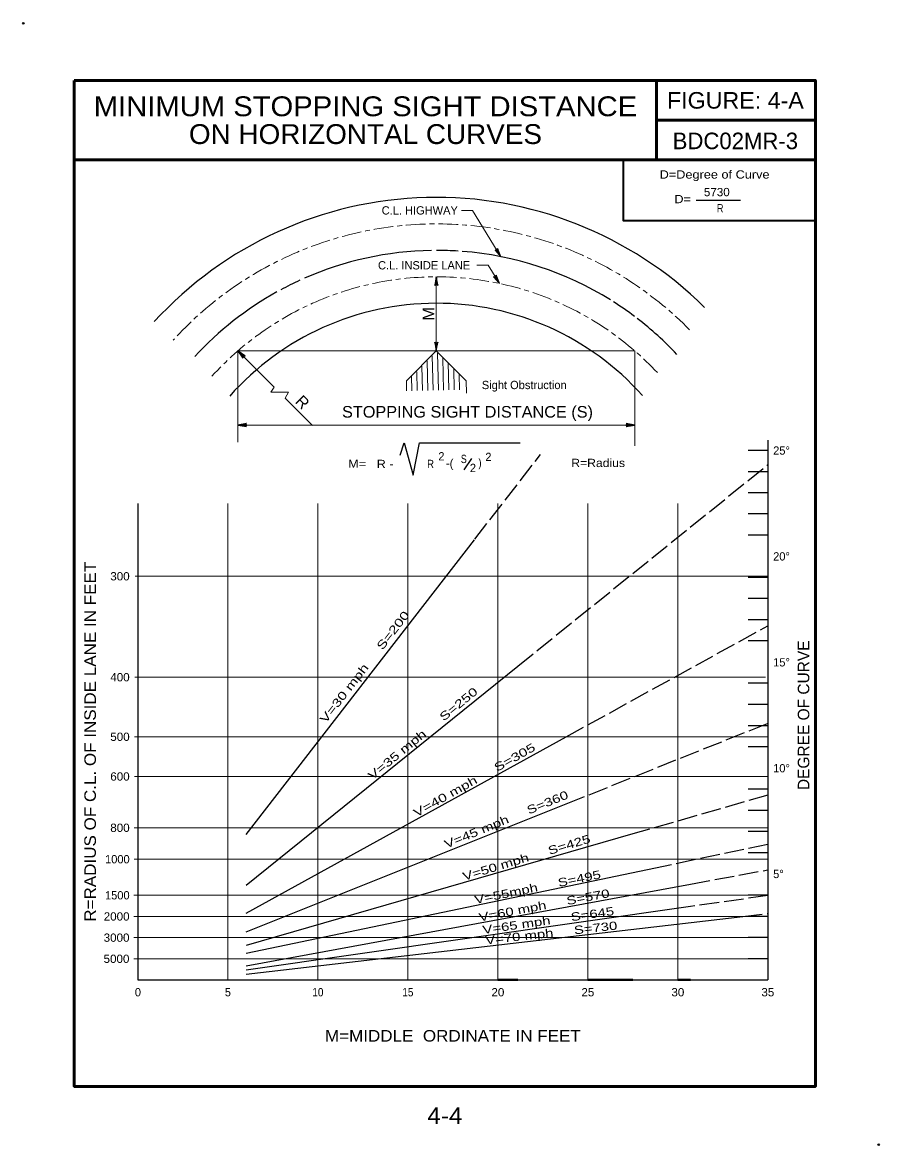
# Model space of a CAD drawing. Extents: x -960 to -151, y 1600 to 2660.
import ezdxf
from ezdxf.enums import TextEntityAlignment as Align

# ---------------------------------------------------------------- set-up
doc = ezdxf.new("R2010")
doc.units = 0
doc.header["$LTSCALE"] = 3.1
doc.header["$PDMODE"] = 32
doc.header["$PDSIZE"] = 1.55
doc.linetypes.add('LONG_DASH_SHORT_DASH', pattern=[9.9, 6, -1.2, 1.5, -1.2])
doc.linetypes.add('LONG_DASHED', pattern=[7.5, 6, -1.5])
doc.layers.add('1', color=7, linetype='Continuous', lineweight=25)
doc.layers.add('24', color=7, linetype='Continuous', lineweight=25)

msp = doc.modelspace()

# ---------------------------------------------------------------- linework, layer by layer
at = {"layer": '1', "lineweight": 53}
for p, q in [((-361.39, 2605.66), (-361.39, 2530.66)), ((-361.39, 2568.16), (-212.6, 2568.16)), ((-911.39, 2530.66), (-211.39, 2530.66))]:
    msp.add_line(p, q, dxfattribs=at)
at = {"layer": '1'}
for p, q in [((-324.14, 2492.71), (-282.05, 2492.71)), ((-256.31, 2265.94), (-256.31, 2256.23)), ((-543.02, 2238.11), (-535.77, 2248.68)), ((-256.31, 2256.23), (-275.06, 2256.23)), ((-256.31, 2256.02), (-256.31, 2156.23)), ((-256.31, 2236.21), (-275.06, 2236.21)), ((-851.31, 2206.23), (-851.31, 1756.23)), ((-256.31, 2216.19), (-275.06, 2216.19)), ((-256.31, 2196.32), (-275.06, 2196.32)), ((-256.31, 2176.27), (-275.06, 2176.27)), ((-749.12, 1893.73), (-533.5, 2171.86)), ((-256.31, 2156.19), (-256.31, 2056.23)), ((-256.31, 2136.37), (-275.06, 2136.37)), ((-256.31, 2116.36), (-275.06, 2116.36)), ((-256.31, 2096.36), (-275.06, 2096.36)), ((-256.31, 2076.43), (-275.06, 2076.43)), ((-749.12, 1845.78), (-492.61, 2052.53)), ((-256.31, 2056.19), (-256.31, 1956.23)), ((-256.31, 2036.41), (-275.06, 2036.41)), ((-256.31, 2016.27), (-275.06, 2016.27)), ((-256.31, 1996.27), (-275.06, 1996.27)), ((-749.12, 1819.48), (-446.71, 1985.92)), ((-256.31, 1976.34), (-275.06, 1976.34)), ((-256.31, 1956.17), (-256.31, 1856.23)), ((-256.31, 1936.32), (-275.06, 1936.32)), ((-749.12, 1801.74), (-446.71, 1922.6)), ((-256.31, 1916.43), (-275.06, 1916.43)), ((-383.81, 1894.11), (-749.12, 1788.94)), ((-256.31, 1896.31), (-275.06, 1896.31)), ((-256.31, 1876.38), (-275.06, 1876.38)), ((-354.91, 1863.56), (-749.12, 1781.37)), ((-256.31, 1856.13), (-256.31, 1756.23)), ((-749.12, 1769.71), (-329.41, 1846.85)), ((-256.31, 1836.36), (-275.06, 1836.36)), ((-329.41, 1825.53), (-749.12, 1765.57)), ((-749.12, 1761.88), (-280.11, 1816.22)), ((-256.31, 1816.34), (-275.06, 1816.34)), ((-256.31, 1796.34), (-275.06, 1796.34)), ((-256.31, 1776.36), (-275.06, 1776.36)), ((-851.31, 1756.23), (-256.31, 1756.23))]:
    msp.add_line(p, q, dxfattribs=at)
at = {"layer": '1', "lineweight": 13}
for p, q in [((-569.46, 2350.28), (-569.46, 2420.28)), ((-756.96, 2350.28), (-381.96, 2350.28)), ((-756.96, 2350.28), (-756.96, 2264.14)), ((-756.96, 2350.28), (-722.77, 2316.18)), ((-569.46, 2350.28), (-597.75, 2321.99)), ((-573.26, 2345.52), (-572.54, 2313.13)), ((-569.46, 2350.28), (-541.17, 2321.99)), ((-568.32, 2348.13), (-567.54, 2313.24)), ((-381.96, 2350.28), (-381.96, 2260.81)), ((-583.06, 2335.99), (-582.54, 2312.91)), ((-578.17, 2341.06), (-577.54, 2313.02)), ((-563.21, 2343.41), (-562.54, 2313.36)), ((-558.12, 2339.43), (-557.54, 2313.47)), ((-552.99, 2333.66), (-552.54, 2313.58)), ((-592.86, 2326.83), (-592.54, 2312.68)), ((-587.94, 2330.41), (-587.54, 2312.79)), ((-547.86, 2328.12), (-547.54, 2313.69)), ((-725.65, 2311.24), (-722.77, 2316.18)), ((-597.75, 2321.99), (-597.54, 2312.57)), ((-541.17, 2321.99), (-540.94, 2310.36)), ((-725.65, 2311.24), (-709.11, 2311.24)), ((-712.31, 2305.74), (-709.11, 2311.24)), ((-712.31, 2305.74), (-686.32, 2279.82)), ((-756.96, 2280.28), (-381.96, 2280.28)), ((-766.31, 2206.23), (-766.31, 1756.23)), ((-681.31, 2206.23), (-681.31, 1756.23)), ((-596.31, 2206.23), (-596.31, 1756.23)), ((-511.31, 2206.23), (-511.31, 1756.23)), ((-426.31, 2206.23), (-426.31, 1756.23)), ((-341.31, 2206.23), (-341.31, 1756.23)), ((-851.31, 2137.48), (-853.99, 2137.48)), ((-257.1, 2137.48), (-851.3, 2137.48)), ((-851.31, 2042.17), (-854.34, 2042.17)), ((-258.62, 2042.17), (-852.82, 2042.17)), ((-851.31, 1985.92), (-854.55, 1985.92)), ((-257.1, 1985.92), (-851.31, 1985.92)), ((-851.31, 1948.42), (-854.69, 1948.42)), ((-257.1, 1948.42), (-851.31, 1948.42)), ((-851.31, 1899.98), (-854.87, 1899.98)), ((-257.1, 1899.98), (-851.31, 1899.98)), ((-851.31, 1870.29), (-854.98, 1870.29)), ((-257.1, 1870.29), (-851.31, 1870.29)), ((-851.12, 1836.22), (-855.11, 1836.23)), ((-256.91, 1836.22), (-851.12, 1836.22)), ((-851.19, 1816.22), (-855.18, 1816.23)), ((-256.5, 1816.22), (-851.19, 1816.22)), ((-851.25, 1796.22), (-855.26, 1796.23)), ((-257.04, 1796.22), (-851.25, 1796.22)), ((-851.31, 1776.23), (-855.33, 1776.25)), ((-256.62, 1776.23), (-851.31, 1776.23))]:
    msp.add_line(p, q, dxfattribs=at)
at = {"layer": '1', "linetype": 'LONG_DASHED'}
for p, q in [((-533.04, 2172.46), (-470.94, 2252.56)), ((-492.61, 2052.53), (-256.31, 2242.99)), ((-446.71, 1985.92), (-256.31, 2090.71)), ((-446.71, 1922.6), (-256.31, 1998.7)), ((-256.31, 1930.81), (-383.81, 1894.11)), ((-256.31, 1884.11), (-354.91, 1863.56)), ((-329.41, 1846.85), (-256.31, 1860.28)), ((-256.31, 1835.98), (-329.41, 1825.53)), ((-280.11, 1816.22), (-256.31, 1818.98))]:
    msp.add_line(p, q, dxfattribs=at)
at = {"layer": '1', "lineweight": 40}
for p, q in [((-511.31, 1756.23), (-492.61, 1756.23)), ((-426.31, 1756.23), (-383.81, 1756.23)), ((-341.31, 1756.23), (-329.41, 1756.23))]:
    msp.add_line(p, q, dxfattribs=at)
at = {"layer": '1', "lineweight": 53}
msp.add_lwpolyline([(-911.39, 2605.66), (-211.39, 2605.66), (-211.39, 1655.66), (-911.39, 1655.66)], close=True, dxfattribs=at)
at = {"layer": '1', "lineweight": 35}
msp.add_lwpolyline([(-392.85, 2530.56), (-392.85, 2473.41), (-211.69, 2473.41)], dxfattribs=at)
at = {"layer": '1'}
msp.add_lwpolyline([(-603.62, 2251.88), (-599.74, 2263.53), (-591.41, 2232.99), (-585.31, 2263.53), (-490.41, 2263.53)], dxfattribs=at)
for centre, radius, start, end in [((-569.46, 2134.164), 361.116, 45.42777, 137.54733), ((-568.951, 2134.459), 310.746, 90.95926, 113.73793), ((-568.951, 2134.459), 310.746, 86.28879, 90.0523), ((-568.951, 2134.459), 310.746, 58.14873, 85.57496), ((-568.951, 2134.459), 310.746, 114.60525, 118.34462), ((-568.951, 2134.459), 310.746, 119.07499, 137.36857), ((-569.46, 2134.164), 261.116, 41.8056, 138.37101), ((-568.951, 2134.459), 310.746, 53.07374, 57.52681), ((-568.951, 2134.459), 310.746, 43.1678, 52.46845)]:
    msp.add_arc(centre, radius, start, end, dxfattribs=at)
at = {"layer": '1', "linetype": 'LONG_DASH_SHORT_DASH', "lineweight": 13}
for radius, start, end in [(336.116, 44.63731, 137.69998), (286.116, 43.14021, 137.79246)]:
    msp.add_arc((-569.46, 2134.164), radius, start, end, dxfattribs=at)
at = {"layer": '1'}
for p in [(-959.6, 2659.68), (-151.6, 1600.68)]:
    msp.add_point(p, dxfattribs=at)
at = {"layer": '24', "lineweight": 13}
for points in [[(-545.72, 2482.84), (-535.28, 2482.84), (-508.47, 2439.26)], [(-531.08, 2431.15), (-520.41, 2431.15), (-509.86, 2414)]]:
    msp.add_lwpolyline(points, dxfattribs=at)
at = {"layer": '24'}
for points in [[(-508.47, 2439.26), (-511.58, 2447.11), (-511.79, 2444.65), (-514.04, 2445.55), (-508.47, 2439.26), (-508.77, 2439.72), (-511.55, 2446.86), (-511.72, 2444.51), (-513.76, 2445.32), (-508.95, 2439.96), (-509.06, 2440.22), (-511.46, 2446.32), (-511.7, 2444.47), (-513.44, 2445.15), (-509.13, 2440.33), (-509.31, 2440.54), (-511.39, 2445.88), (-511.65, 2444.43), (-513.1, 2444.85), (-509.73, 2441.23), (-509.97, 2441.63), (-511.35, 2445.41), (-511.58, 2444.37), (-512.72, 2444.64), (-509.98, 2441.72), (-510.19, 2442.11), (-511.32, 2444.9), (-511.51, 2444.12), (-512.32, 2444.35), (-510.43, 2442.44), (-510.61, 2442.82), (-511.26, 2444.52), (-511.44, 2444.06), (-512.08, 2444.24), (-510.76, 2442.99), (-511.14, 2444.12), (-511.32, 2443.81), (-511.86, 2444.08), (-510.95, 2443.21), (-511.19, 2443.96), (-511.23, 2443.56), (-511.55, 2443.79), (-511.16, 2443.6), (-511.23, 2443.79)], [(-569.46, 2420.28), (-570.93, 2411.96), (-569.46, 2413.95), (-568.01, 2412.01), (-569.46, 2420.28), (-569.45, 2419.73), (-570.82, 2412.2), (-569.44, 2414.11), (-568.13, 2412.34), (-569.42, 2419.43), (-569.46, 2419.15), (-570.61, 2412.7), (-569.44, 2414.15), (-568.31, 2412.66), (-569.46, 2419.03), (-569.42, 2418.75), (-570.44, 2413.11), (-569.46, 2414.21), (-568.45, 2413.09), (-569.42, 2417.95), (-569.42, 2417.48), (-570.23, 2413.53), (-569.48, 2414.3), (-568.66, 2413.47), (-569.46, 2417.39), (-569.49, 2416.95), (-569.99, 2413.98), (-569.42, 2414.55), (-568.85, 2413.93), (-569.46, 2416.54), (-569.5, 2416.12), (-569.84, 2414.34), (-569.44, 2414.63), (-569, 2414.15), (-569.46, 2415.91), (-569.74, 2414.74), (-569.42, 2414.91), (-569.1, 2414.4), (-569.42, 2415.61), (-569.61, 2414.85), (-569.36, 2415.17), (-569.21, 2414.8), (-569.44, 2415.17), (-569.48, 2414.98)], [(-509.86, 2414), (-512.97, 2421.85), (-513.18, 2419.39), (-515.43, 2420.29), (-509.86, 2414), (-510.16, 2414.46), (-512.94, 2421.6), (-513.11, 2419.25), (-515.15, 2420.06), (-510.34, 2414.7), (-510.45, 2414.96), (-512.85, 2421.06), (-513.09, 2419.21), (-514.83, 2419.89), (-510.52, 2415.07), (-510.7, 2415.28), (-512.78, 2420.62), (-513.04, 2419.17), (-514.49, 2419.59), (-511.12, 2415.97), (-511.36, 2416.37), (-512.74, 2420.15), (-512.97, 2419.11), (-514.11, 2419.38), (-511.37, 2416.46), (-511.58, 2416.85), (-512.71, 2419.64), (-512.9, 2418.86), (-513.71, 2419.09), (-511.82, 2417.18), (-512, 2417.56), (-512.65, 2419.26), (-512.83, 2418.8), (-513.47, 2418.98), (-512.15, 2417.73), (-512.53, 2418.86), (-512.71, 2418.55), (-513.25, 2418.82), (-512.34, 2417.95), (-512.58, 2418.7), (-512.62, 2418.3), (-512.94, 2418.53), (-512.55, 2418.34), (-512.62, 2418.53)], [(-569.46, 2350.28), (-567.99, 2358.6), (-569.46, 2356.61), (-570.91, 2358.55), (-569.46, 2350.28), (-569.48, 2350.83), (-568.1, 2358.36), (-569.48, 2356.45), (-570.79, 2358.22), (-569.5, 2351.13), (-569.46, 2351.41), (-568.31, 2357.86), (-569.48, 2356.41), (-570.61, 2357.9), (-569.46, 2351.53), (-569.5, 2351.81), (-568.48, 2357.45), (-569.46, 2356.35), (-570.47, 2357.47), (-569.5, 2352.61), (-569.5, 2353.08), (-568.69, 2357.03), (-569.44, 2356.26), (-570.26, 2357.09), (-569.46, 2353.17), (-569.43, 2353.61), (-568.93, 2356.58), (-569.5, 2356.01), (-570.07, 2356.63), (-569.46, 2354.02), (-569.42, 2354.44), (-569.08, 2356.22), (-569.48, 2355.93), (-569.92, 2356.41), (-569.46, 2354.65), (-569.18, 2355.82), (-569.5, 2355.65), (-569.82, 2356.16), (-569.5, 2354.95), (-569.31, 2355.71), (-569.56, 2355.39), (-569.71, 2355.76), (-569.48, 2355.39), (-569.44, 2355.58)], [(-756.96, 2350.28), (-752.11, 2343.37), (-752.48, 2345.81), (-750.08, 2345.46), (-756.96, 2350.28), (-756.56, 2349.9), (-752.2, 2343.61), (-752.58, 2345.93), (-750.4, 2345.62), (-756.33, 2349.71), (-756.16, 2349.48), (-752.4, 2344.12), (-752.61, 2345.96), (-750.76, 2345.71), (-756.07, 2349.39), (-755.85, 2349.23), (-752.57, 2344.53), (-752.66, 2345.99), (-751.15, 2345.92), (-755.28, 2348.66), (-754.95, 2348.33), (-752.72, 2344.97), (-752.74, 2346.04), (-751.57, 2346.04), (-754.92, 2348.24), (-754.62, 2347.91), (-752.88, 2345.45), (-752.87, 2346.26), (-752.03, 2346.23), (-754.31, 2347.64), (-754.05, 2347.31), (-753.02, 2345.81), (-752.95, 2346.31), (-752.29, 2346.28), (-753.86, 2347.19), (-753.24, 2346.17), (-753.13, 2346.52), (-752.54, 2346.38), (-753.63, 2347.01), (-753.22, 2346.34), (-753.27, 2346.74), (-752.9, 2346.59), (-753.33, 2346.68), (-753.22, 2346.52)], [(-756.96, 2280.28), (-748.64, 2278.81), (-750.63, 2280.28), (-748.69, 2281.73), (-756.96, 2280.28), (-756.41, 2280.3), (-748.88, 2278.92), (-750.79, 2280.3), (-749.02, 2281.61), (-756.11, 2280.32), (-755.83, 2280.28), (-749.38, 2279.13), (-750.83, 2280.3), (-749.34, 2281.43), (-755.71, 2280.28), (-755.43, 2280.32), (-749.79, 2279.3), (-750.89, 2280.28), (-749.77, 2281.29), (-754.63, 2280.32), (-754.16, 2280.32), (-750.21, 2279.51), (-750.98, 2280.26), (-750.15, 2281.08), (-754.07, 2280.28), (-753.63, 2280.25), (-750.66, 2279.75), (-751.23, 2280.32), (-750.61, 2280.89), (-753.22, 2280.28), (-752.8, 2280.24), (-751.02, 2279.9), (-751.31, 2280.3), (-750.83, 2280.74), (-752.59, 2280.28), (-751.42, 2280), (-751.59, 2280.32), (-751.08, 2280.64), (-752.29, 2280.32), (-751.53, 2280.13), (-751.85, 2280.38), (-751.48, 2280.53), (-751.85, 2280.3), (-751.66, 2280.26)], [(-381.96, 2280.28), (-390.28, 2281.75), (-388.29, 2280.28), (-390.23, 2278.83), (-381.96, 2280.28), (-382.51, 2280.27), (-390.04, 2281.64), (-388.13, 2280.26), (-389.9, 2278.95), (-382.81, 2280.24), (-383.09, 2280.28), (-389.54, 2281.43), (-388.09, 2280.26), (-389.58, 2279.13), (-383.21, 2280.28), (-383.49, 2280.24), (-389.13, 2281.26), (-388.03, 2280.28), (-389.15, 2279.27), (-384.29, 2280.24), (-384.76, 2280.24), (-388.71, 2281.05), (-387.94, 2280.3), (-388.77, 2279.48), (-384.85, 2280.28), (-385.29, 2280.31), (-388.26, 2280.81), (-387.69, 2280.24), (-388.31, 2279.67), (-385.7, 2280.28), (-386.12, 2280.32), (-387.9, 2280.66), (-387.61, 2280.26), (-388.09, 2279.82), (-386.33, 2280.28), (-387.5, 2280.56), (-387.33, 2280.24), (-387.84, 2279.92), (-386.63, 2280.24), (-387.39, 2280.43), (-387.07, 2280.18), (-387.44, 2280.03), (-387.07, 2280.26), (-387.26, 2280.3)]]:
    msp.add_lwpolyline(points, dxfattribs=at)

# ---------------------------------------------------------------- texts
at = {"layer": '1'}
for s, height, width, p in [('MINIMUM STOPPING SIGHT DISTANCE', 18.75, 1.1, (-636.395, 2571.91)), ('FIGURE: 4-A', 15.63, 1.05, (-287, 2579.09)), ('ON HORIZONTAL CURVES', 18.75, 1.05, (-636.39, 2545.66)), ('D=Degree of Curve', 7.81, 1.15, (-306.645, 2513.01)), ('5730', 7.81, 1.05, (-304.525, 2496.37)), ('D=', 7.81, 1.15, (-336.81, 2489.77)), ('R', 7.81, 0.85, (-301.385, 2481.09)), ('STOPPING SIGHT DISTANCE (S)', 10.93, 1.05, (-540.02, 2287.31)), ('S', 7.81, 0.8, (-543.51, 2244.39)), ('10', 7.81, 0.9, (-681.315, 1740.8)), ('15', 7.81, 0.9, (-596.315, 1740.8)), ('20', 7.81, 1.05, (-511.315, 1740.8)), ('25', 7.81, 1.05, (-426.315, 1740.8)), ('30', 7.81, 1.05, (-341.315, 1740.8)), ('35', 7.81, 1.05, (-256.315, 1740.8)), ('M=MIDDLE  ORDINATE IN FEET', 10.93, 1.1, (-553.81, 1698.05)), ('4-4', 15.63, 1.1, (-561.39, 1620.35))]:
    msp.add_text(s, height=height, dxfattribs=dict(at, width=width)).set_placement(p, align=Align.CENTER)
for s, height, p in [('BDC02MR-3', 15.63, (-287.005, 2540.8)), ('C.L. HIGHWAY', 7.81, (-585.115, 2479.09)), ('C.L. INSIDE LANE', 7.81, (-581, 2427.24)), ('Sight Obstruction', 7.81, (-486.425, 2314.21)), ('0', 7.81, (-851.31, 1740.8)), ('5', 7.81, (-766.31, 1740.8))]:
    msp.add_text(s, height=height, dxfattribs=at).set_placement(p, align=Align.CENTER)
for s, height, rotation, width, p in [('M', 10.93, 90, 1.05, (-571.46, 2385.275)), ('R=RADIUS OF C.L. OF INSIDE LANE IN FEET', 10.93, 90, 1.1, (-890.99, 1981.225)), ('V=30 mph     S=200', 7.81, 52.214, 1.4, (-634.086, 2049.452)), ('V=35 mph     S=250', 7.81, 39.417, 1.4, (-579.755, 1985.996)), ('V=40 mph     S=305', 7.81, 29.377, 1.4, (-531.651, 1941.683)), ('V=45 mph     S=360', 7.81, 22.453, 1.35, (-501.911, 1904.237)), ('V=50 mph     S=425', 7.81, 16.871, 1.35, (-483.168, 1868.097)), ('V=55mph     S=495', 7.81, 11.606, 1.35, (-472.981, 1840.136)), ('V=60 mph     S=570', 7.81, 10.642, 1.35, (-466.891, 1822.978)), ('V=65 mph     S=645', 7.81, 8.286, 1.35, (-463.148, 1808.639)), ('V=70 mph     S=730', 7.81, 6.512, 1.35, (-460.463, 1796.851))]:
    msp.add_text(s, height=height, rotation=rotation, dxfattribs=dict(at, width=width)).set_placement(p, align=Align.CENTER)
for s, rotation, p in [('R', 315, (-699.678, 2298.028)), ('DEGREE OF CURVE', 90, (-217.14, 2006.21))]:
    msp.add_text(s, height=10.93, rotation=rotation, dxfattribs=at).set_placement(p, align=Align.CENTER)
for s, p in [('25°', (-251.31, 2252.32)), ('2', (-567.55, 2246.87)), ('-(', (-560.34, 2240.2)), ('2', (-523.15, 2246.31)), ('2', (-537.77, 2235.88)), ('20°', (-251.31, 2152.35)), ('15°', (-251.31, 2052.32)), ('10°', (-251.31, 1952.3)), ('5°', (-251.31, 1852.46))]:
    msp.add_text(s, height=7.81, dxfattribs=at).set_placement(p)
for s, width, p in [(')', 0.9, (-529.81, 2240.75)), ('R=Radius', 1.1, (-441.99, 2240.61)), ('M=', 1.15, (-652.75, 2239.92)), ('R -', 1.15, (-625.82, 2239.64)), ('R', 0.85, (-578.1, 2239.64))]:
    msp.add_text(s, height=7.81, dxfattribs=dict(at, width=width)).set_placement(p)
at = {"layer": '1', "width": 1.05}
for s, p in [('300', (-859.12, 2133.57)), ('400', (-859.12, 2038.26)), ('500', (-859.12, 1982.01)), ('600', (-859.12, 1944.51)), ('800', (-859.12, 1896.07)), ('2000', (-859.22, 1812.33)), ('3000', (-859.29, 1792.33)), ('5000', (-859.35, 1772.35))]:
    msp.add_text(s, height=7.81, dxfattribs=at).set_placement(p, align=Align.RIGHT)
at = {"layer": '1'}
for s, p in [('1000', (-859.12, 1866.38)), ('1500', (-859.16, 1832.33))]:
    msp.add_text(s, height=7.81, dxfattribs=at).set_placement(p, align=Align.RIGHT)

doc.saveas('drawing.dxf')
